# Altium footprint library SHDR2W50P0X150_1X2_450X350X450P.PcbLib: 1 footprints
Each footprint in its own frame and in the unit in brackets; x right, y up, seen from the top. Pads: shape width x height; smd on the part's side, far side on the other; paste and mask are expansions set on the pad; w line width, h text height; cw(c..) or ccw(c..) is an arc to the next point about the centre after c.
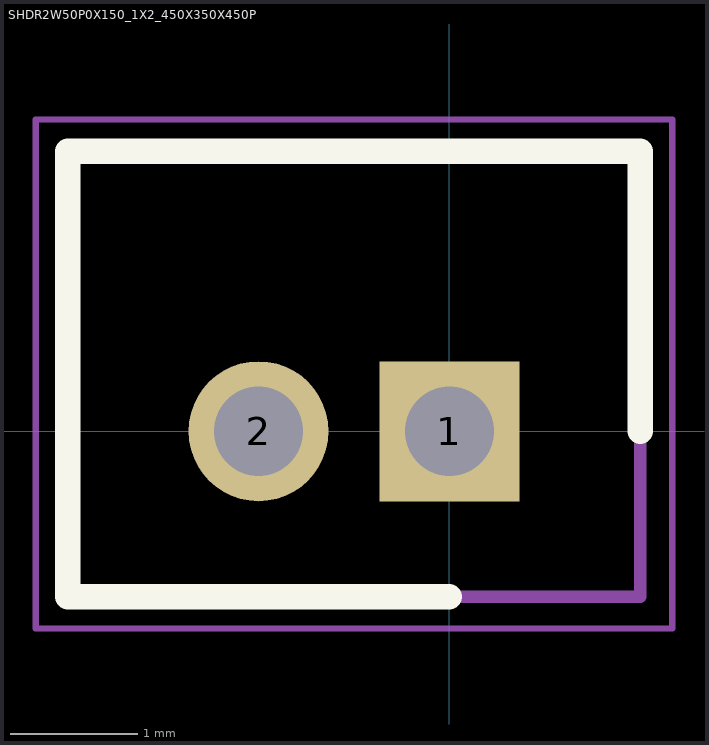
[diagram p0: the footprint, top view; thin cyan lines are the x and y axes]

## SHDR2W50P0X150_1X2_450X350X450P [mm]
pads (2):
  rect 1.1x1.1 / inner round 1.1 / far side rect 1.1x1.1 hole 0.7: 1(0,0)
  round 1.1 hole 0.7: 2(-1.5,0)
Top Overlay:
  lines w0.2: 0,-1.3 -3,-1.3 -3,2.2 1.5,2.2 1.5,0
Mechanical 15:
  lines w0.1: -3,-1.3 1.5,-1.3 1.5,2.2 -3,2.2 -3,-1.3
Mechanical 20:
  lines w0.05: -3.25,-1.55 1.75,-1.55 1.75,2.45 -3.25,2.45 -3.25,-1.55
